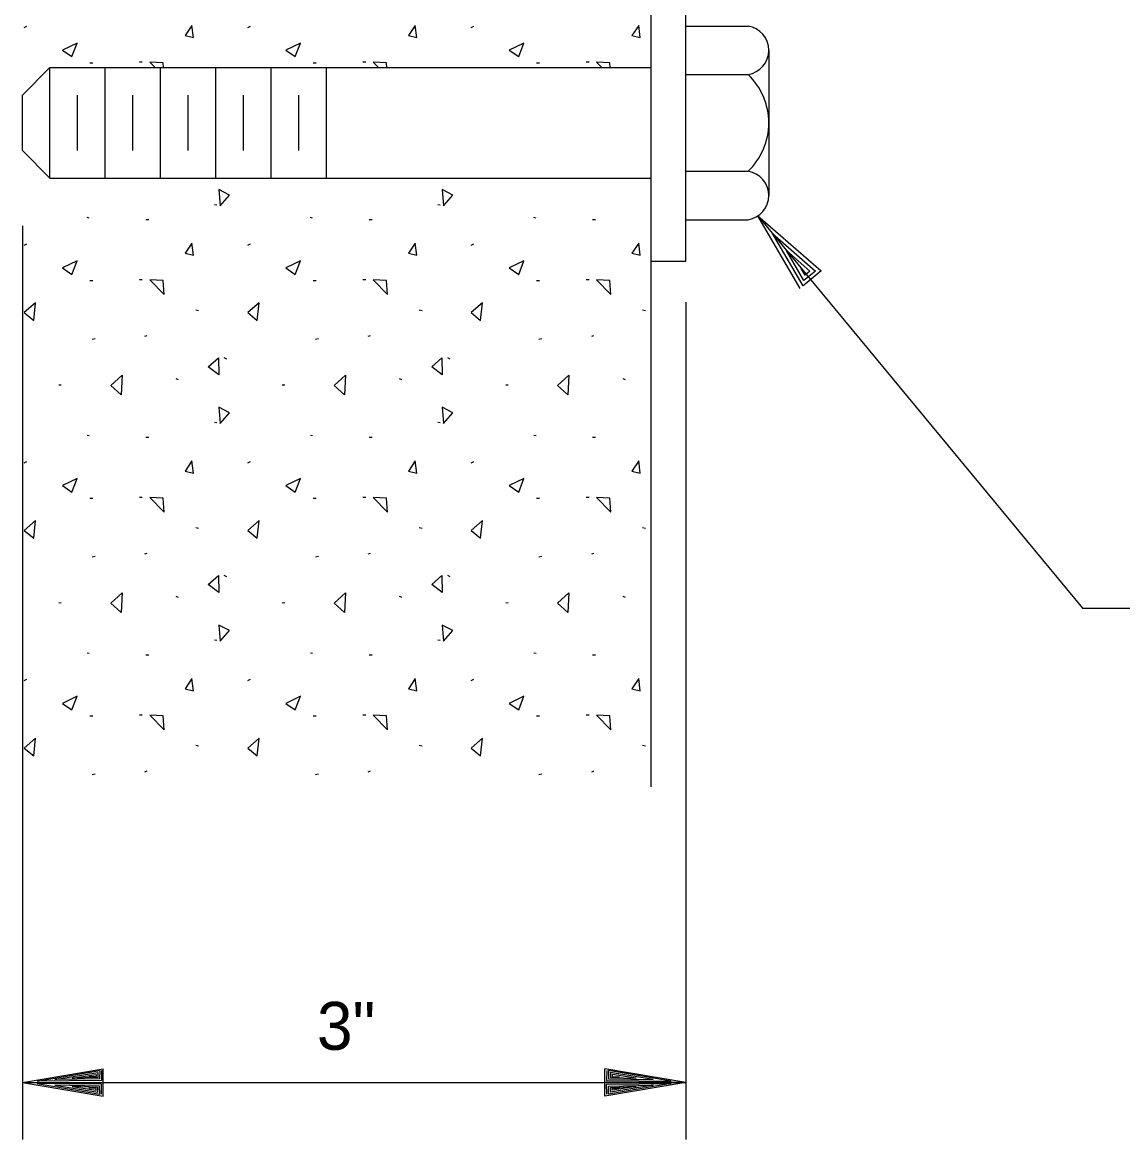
# Model space of a CAD drawing. Extents: x 44742.55 to 44745.38, y 44738.95 to 44741.13.
# Drawn here: x 44743.7411 to 44743.9484, y 44739.2677 to 44739.478 of the extents above; entities that cross this region are included whole.
import ezdxf

# ---------------------------------------------------------------- set-up
doc = ezdxf.new("R2010")
doc.units = 0
for name, color, linetype in [('G-ANNO-PATT', 7, 'Continuous'), ('Level 1', 7, 'Continuous'), ('Level 10', 7, 'Continuous'), ('Level 2', 7, 'Continuous'), ('Level 4', 7, 'Continuous')]:
    doc.layers.add(name, color=color, linetype=linetype)

msp = doc.modelspace()

# ---------------------------------------------------------------- linework, layer by layer
at = {"layer": 'G-ANNO-PATT'}
for p, q in [((44743.741951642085, 44739.47728637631), (44743.74145164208, 44739.4770363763)), ((44743.78403497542, 44739.47728637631), (44743.78353497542, 44739.4770363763)), ((44743.826118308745, 44739.47728637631), (44743.82561830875, 44739.4770363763)), ((44743.754409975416, 44739.470369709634), (44743.75384747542, 44739.470369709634)), ((44743.76374330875, 44739.470567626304), (44743.76321205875, 44739.470567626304)), ((44743.79649330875, 44739.470369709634), (44743.79593080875, 44739.470369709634)), ((44743.805826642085, 44739.470567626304), (44743.805295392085, 44739.470567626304)), ((44743.83857664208, 44739.470369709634), (44743.83801414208, 44739.470369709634)), ((44743.84790997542, 44739.470567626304), (44743.84737872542, 44739.470567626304)), ((44743.77777455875, 44739.44364054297), (44743.77735789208, 44739.44367179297)), ((44743.819857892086, 44739.44364054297), (44743.819441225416, 44739.44367179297)), ((44743.75374330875, 44739.44120304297), (44743.75332664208, 44739.44127595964)), ((44743.79582664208, 44739.44120304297), (44743.79540997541, 44739.44127595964)), ((44743.83790997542, 44739.44120304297), (44743.83749330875, 44739.44127595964)), ((44743.76495164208, 44739.4408488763), (44743.76438914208, 44739.4408488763)), ((44743.80703497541, 44739.4408488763), (44743.806472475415, 44739.4408488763)), ((44743.849118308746, 44739.4408488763), (44743.84855580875, 44739.4408488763)), ((44743.741951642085, 44739.43629679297), (44743.74145164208, 44739.43604679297)), ((44743.78403497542, 44739.43629679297), (44743.78353497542, 44739.43604679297)), ((44743.826118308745, 44739.43629679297), (44743.82561830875, 44739.43604679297)), ((44743.754409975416, 44739.429380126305), (44743.75384747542, 44739.429380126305)), ((44743.76374330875, 44739.42957804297), (44743.76321205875, 44739.42957804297)), ((44743.79649330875, 44739.429380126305), (44743.79593080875, 44739.429380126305)), ((44743.805826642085, 44739.42957804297), (44743.805295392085, 44739.42957804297)), ((44743.83857664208, 44739.429380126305), (44743.83801414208, 44739.429380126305)), ((44743.84790997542, 44739.42957804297), (44743.84737872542, 44739.42957804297)), ((44743.77434747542, 44739.42375512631), (44743.77380580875, 44739.4238488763)), ((44743.81643080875, 44739.42375512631), (44743.81588914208, 44739.4238488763)), ((44743.858514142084, 44739.42375512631), (44743.857972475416, 44739.4238488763)), ((44743.75485789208, 44739.4184738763), (44743.75429539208, 44739.4183176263)), ((44743.764566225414, 44739.419036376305), (44743.76415997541, 44739.4188801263)), ((44743.79694122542, 44739.4184738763), (44743.79637872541, 44739.4183176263)), ((44743.80664955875, 44739.419036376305), (44743.80624330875, 44739.4188801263)), ((44743.83902455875, 44739.4184738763), (44743.838462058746, 44739.4183176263)), ((44743.84873289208, 44739.419036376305), (44743.84832664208, 44739.4188801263)), ((44743.779649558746, 44739.414619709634), (44743.77918080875, 44739.41490095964)), ((44743.82173289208, 44739.414619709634), (44743.82126414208, 44739.41490095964)), ((44743.74848289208, 44739.409744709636), (44743.74802455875, 44739.40970304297)), ((44743.770576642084, 44739.41074470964), (44743.77012872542, 44739.41095304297)), ((44743.79056622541, 44739.409744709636), (44743.790107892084, 44739.40970304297)), ((44743.81265997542, 44739.41074470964), (44743.81221205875, 44739.41095304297)), ((44743.832649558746, 44739.409744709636), (44743.83219122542, 44739.40970304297)), ((44743.85474330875, 44739.41074470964), (44743.854295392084, 44739.41095304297)), ((44743.77777455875, 44739.40265095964), (44743.77735789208, 44739.402682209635)), ((44743.819857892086, 44739.40265095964), (44743.819441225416, 44739.402682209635)), ((44743.75374330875, 44739.40021345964), (44743.75332664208, 44739.4002863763)), ((44743.76495164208, 44739.39985929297), (44743.76438914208, 44739.39985929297)), ((44743.79582664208, 44739.40021345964), (44743.79540997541, 44739.4002863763)), ((44743.80703497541, 44739.39985929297), (44743.806472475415, 44739.39985929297)), ((44743.83790997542, 44739.40021345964), (44743.83749330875, 44739.4002863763)), ((44743.849118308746, 44739.39985929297), (44743.84855580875, 44739.39985929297)), ((44743.741951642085, 44739.395307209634), (44743.74145164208, 44739.39505720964)), ((44743.78403497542, 44739.395307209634), (44743.78353497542, 44739.39505720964)), ((44743.826118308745, 44739.395307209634), (44743.82561830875, 44739.39505720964)), ((44743.754409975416, 44739.38839054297), (44743.75384747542, 44739.38839054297)), ((44743.76374330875, 44739.38858845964), (44743.76321205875, 44739.38858845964)), ((44743.79649330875, 44739.38839054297), (44743.79593080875, 44739.38839054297)), ((44743.805826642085, 44739.38858845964), (44743.805295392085, 44739.38858845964)), ((44743.83857664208, 44739.38839054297), (44743.83801414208, 44739.38839054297)), ((44743.84790997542, 44739.38858845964), (44743.84737872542, 44739.38858845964)), ((44743.77434747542, 44739.38276554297), (44743.77380580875, 44739.38285929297)), ((44743.81643080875, 44739.38276554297), (44743.81588914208, 44739.38285929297)), ((44743.858514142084, 44739.38276554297), (44743.857972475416, 44739.38285929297)), ((44743.75485789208, 44739.37748429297), (44743.75429539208, 44739.37732804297)), ((44743.764566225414, 44739.37804679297), (44743.76415997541, 44739.37789054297)), ((44743.79694122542, 44739.37748429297), (44743.79637872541, 44739.37732804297)), ((44743.80664955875, 44739.37804679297), (44743.80624330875, 44739.37789054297)), ((44743.83902455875, 44739.37748429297), (44743.838462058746, 44739.37732804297)), ((44743.84873289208, 44739.37804679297), (44743.84832664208, 44739.37789054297)), ((44743.779649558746, 44739.373630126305), (44743.77918080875, 44739.3739113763)), ((44743.82173289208, 44739.373630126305), (44743.82126414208, 44739.3739113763)), ((44743.770576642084, 44739.3697551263), (44743.77012872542, 44739.369963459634)), ((44743.81265997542, 44739.3697551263), (44743.81221205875, 44739.369963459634)), ((44743.74848289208, 44739.36875512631), (44743.74802455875, 44739.36871345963)), ((44743.79056622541, 44739.36875512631), (44743.790107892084, 44739.36871345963)), ((44743.832649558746, 44739.36875512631), (44743.83219122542, 44739.36871345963)), ((44743.77777455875, 44739.3616613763), (44743.77735789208, 44739.361692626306)), ((44743.819857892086, 44739.3616613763), (44743.819441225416, 44739.361692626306)), ((44743.75374330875, 44739.3592238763), (44743.75332664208, 44739.35929679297)), ((44743.79582664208, 44739.3592238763), (44743.79540997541, 44739.35929679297)), ((44743.83790997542, 44739.3592238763), (44743.83749330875, 44739.35929679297)), ((44743.76495164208, 44739.358869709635), (44743.76438914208, 44739.358869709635)), ((44743.80703497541, 44739.358869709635), (44743.806472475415, 44739.358869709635)), ((44743.849118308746, 44739.358869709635), (44743.84855580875, 44739.358869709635)), ((44743.741951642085, 44739.354317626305), (44743.74145164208, 44739.3540676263)), ((44743.78403497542, 44739.354317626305), (44743.78353497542, 44739.3540676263)), ((44743.826118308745, 44739.354317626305), (44743.82561830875, 44739.3540676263)), ((44743.754409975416, 44739.34740095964), (44743.75384747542, 44739.34740095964)), ((44743.76374330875, 44739.3475988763), (44743.76321205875, 44739.3475988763)), ((44743.79649330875, 44739.34740095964), (44743.79593080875, 44739.34740095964)), ((44743.805826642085, 44739.3475988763), (44743.805295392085, 44739.3475988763)), ((44743.83857664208, 44739.34740095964), (44743.83801414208, 44739.34740095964)), ((44743.84790997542, 44739.3475988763), (44743.84737872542, 44739.3475988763)), ((44743.77434747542, 44739.341775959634), (44743.77380580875, 44739.341869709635)), ((44743.81643080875, 44739.341775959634), (44743.81588914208, 44739.341869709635)), ((44743.858514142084, 44739.341775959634), (44743.857972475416, 44739.341869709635)), ((44743.75485789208, 44739.336494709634), (44743.75429539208, 44739.33633845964)), ((44743.764566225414, 44739.33705720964), (44743.76415997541, 44739.336900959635)), ((44743.79694122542, 44739.336494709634), (44743.79637872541, 44739.33633845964)), ((44743.80664955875, 44739.33705720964), (44743.80624330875, 44739.336900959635)), ((44743.83902455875, 44739.336494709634), (44743.838462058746, 44739.33633845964)), ((44743.84873289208, 44739.33705720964), (44743.84832664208, 44739.336900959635))]:
    msp.add_line(p, q, dxfattribs=at)
for points in [[(44743.77336830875, 44739.47517179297), (44743.77307664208, 44739.47745304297), (44743.77179539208, 44739.47554679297)], [(44743.815451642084, 44739.47517179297), (44743.81515997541, 44739.47745304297), (44743.813878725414, 44739.47554679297)], [(44743.85753497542, 44739.47517179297), (44743.85724330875, 44739.47745304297), (44743.85596205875, 44739.47554679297)], [(44743.75047247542, 44739.47158845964), (44743.751462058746, 44739.47414054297), (44743.748701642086, 44739.47279679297)], [(44743.79255580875, 44739.47158845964), (44743.79354539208, 44739.47414054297), (44743.79078497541, 44739.47279679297)], [(44743.834639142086, 44739.47158845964), (44743.835628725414, 44739.47414054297), (44743.832868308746, 44739.47279679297)], [(44743.778378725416, 44739.44349470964), (44743.78015997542, 44739.44549470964), (44743.778170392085, 44739.44655720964)], [(44743.82046205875, 44739.44349470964), (44743.82224330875, 44739.44549470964), (44743.82025372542, 44739.44655720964)], [(44743.77336830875, 44739.43418220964), (44743.77307664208, 44739.436463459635), (44743.77179539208, 44739.434557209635)], [(44743.815451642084, 44739.43418220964), (44743.81515997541, 44739.436463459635), (44743.813878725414, 44739.434557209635)], [(44743.85753497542, 44739.43418220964), (44743.85724330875, 44739.436463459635), (44743.85596205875, 44739.434557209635)], [(44743.75047247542, 44739.4305988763), (44743.751462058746, 44739.43315095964), (44743.748701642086, 44739.431807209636)], [(44743.79255580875, 44739.4305988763), (44743.79354539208, 44739.43315095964), (44743.79078497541, 44739.431807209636)], [(44743.834639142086, 44739.4305988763), (44743.835628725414, 44739.43315095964), (44743.832868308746, 44739.431807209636)], [(44743.76764955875, 44739.4294426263), (44743.76514955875, 44739.42957804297), (44743.76785789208, 44739.42680720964)], [(44743.809732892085, 44739.4294426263), (44743.80723289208, 44739.42957804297), (44743.809941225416, 44739.42680720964)], [(44743.85181622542, 44739.4294426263), (44743.849316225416, 44739.42957804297), (44743.85202455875, 44739.42680720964)], [(44743.743639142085, 44739.425255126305), (44743.74150372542, 44739.42339054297), (44743.74327455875, 44739.421900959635)], [(44743.78572247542, 44739.425255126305), (44743.78358705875, 44739.42339054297), (44743.785357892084, 44739.421900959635)], [(44743.827805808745, 44739.425255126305), (44743.825670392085, 44739.42339054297), (44743.82744122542, 44739.421900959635)], [(44743.778170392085, 44739.41167179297), (44743.776170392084, 44739.41318220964), (44743.77808705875, 44739.4148801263)], [(44743.82025372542, 44739.41167179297), (44743.81825372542, 44739.41318220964), (44743.82017039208, 44739.4148801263)], [(44743.75974330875, 44739.4079113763), (44743.757816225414, 44739.4096926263), (44743.75995164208, 44739.4115988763)], [(44743.801826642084, 44739.4079113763), (44743.79989955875, 44739.4096926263), (44743.802034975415, 44739.4115988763)], [(44743.84390997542, 44739.4079113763), (44743.84198289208, 44739.4096926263), (44743.84411830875, 44739.4115988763)], [(44743.778378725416, 44739.4025051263), (44743.78015997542, 44739.4045051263), (44743.778170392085, 44739.4055676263)], [(44743.82046205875, 44739.4025051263), (44743.82224330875, 44739.4045051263), (44743.82025372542, 44739.4055676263)], [(44743.77336830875, 44739.3931926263), (44743.77307664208, 44739.395473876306), (44743.77179539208, 44739.393567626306)], [(44743.815451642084, 44739.3931926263), (44743.81515997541, 44739.395473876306), (44743.813878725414, 44739.393567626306)], [(44743.85753497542, 44739.3931926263), (44743.85724330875, 44739.395473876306), (44743.85596205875, 44739.393567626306)], [(44743.75047247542, 44739.38960929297), (44743.751462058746, 44739.3921613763), (44743.748701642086, 44739.39081762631)], [(44743.79255580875, 44739.38960929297), (44743.79354539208, 44739.3921613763), (44743.79078497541, 44739.39081762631)], [(44743.834639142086, 44739.38960929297), (44743.835628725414, 44739.3921613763), (44743.832868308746, 44739.39081762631)], [(44743.76764955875, 44739.38845304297), (44743.76514955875, 44739.38858845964), (44743.76785789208, 44739.3858176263)], [(44743.809732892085, 44739.38845304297), (44743.80723289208, 44739.38858845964), (44743.809941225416, 44739.3858176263)], [(44743.85181622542, 44739.38845304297), (44743.849316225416, 44739.38858845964), (44743.85202455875, 44739.3858176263)], [(44743.743639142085, 44739.38426554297), (44743.74150372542, 44739.382400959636), (44743.74327455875, 44739.380911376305)], [(44743.78572247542, 44739.38426554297), (44743.78358705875, 44739.382400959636), (44743.785357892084, 44739.380911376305)], [(44743.827805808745, 44739.38426554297), (44743.825670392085, 44739.382400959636), (44743.82744122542, 44739.380911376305)], [(44743.778170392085, 44739.370682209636), (44743.776170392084, 44739.3721926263), (44743.77808705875, 44739.37389054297)], [(44743.82025372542, 44739.370682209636), (44743.81825372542, 44739.3721926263), (44743.82017039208, 44739.37389054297)], [(44743.75974330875, 44739.36692179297), (44743.757816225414, 44739.36870304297), (44743.75995164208, 44739.37060929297)], [(44743.801826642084, 44739.36692179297), (44743.79989955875, 44739.36870304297), (44743.802034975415, 44739.37060929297)], [(44743.84390997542, 44739.36692179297), (44743.84198289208, 44739.36870304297), (44743.84411830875, 44739.37060929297)], [(44743.778378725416, 44739.36151554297), (44743.78015997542, 44739.36351554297), (44743.778170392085, 44739.36457804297)], [(44743.82046205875, 44739.36151554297), (44743.82224330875, 44739.36351554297), (44743.82025372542, 44739.36457804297)], [(44743.77336830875, 44739.35220304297), (44743.77307664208, 44739.35448429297), (44743.77179539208, 44739.35257804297)], [(44743.815451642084, 44739.35220304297), (44743.81515997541, 44739.35448429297), (44743.813878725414, 44739.35257804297)], [(44743.85753497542, 44739.35220304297), (44743.85724330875, 44739.35448429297), (44743.85596205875, 44739.35257804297)], [(44743.75047247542, 44739.348619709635), (44743.751462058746, 44739.35117179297), (44743.748701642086, 44739.34982804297)], [(44743.79255580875, 44739.348619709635), (44743.79354539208, 44739.35117179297), (44743.79078497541, 44739.34982804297)], [(44743.834639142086, 44739.348619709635), (44743.835628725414, 44739.35117179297), (44743.832868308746, 44739.34982804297)], [(44743.76764955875, 44739.347463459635), (44743.76514955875, 44739.3475988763), (44743.76785789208, 44739.34482804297)], [(44743.809732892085, 44739.347463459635), (44743.80723289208, 44739.3475988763), (44743.809941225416, 44739.34482804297)], [(44743.85181622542, 44739.347463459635), (44743.849316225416, 44739.3475988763), (44743.85202455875, 44739.34482804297)], [(44743.743639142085, 44739.34327595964), (44743.74150372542, 44739.34141137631), (44743.74327455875, 44739.33992179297)], [(44743.78572247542, 44739.34327595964), (44743.78358705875, 44739.34141137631), (44743.785357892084, 44739.33992179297)], [(44743.827805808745, 44739.34327595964), (44743.825670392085, 44739.34141137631), (44743.82744122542, 44739.33992179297)]]:
    msp.add_lwpolyline(points, close=True, dxfattribs=at)
for points in [[(44743.76764955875, 44739.47043220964), (44743.76514955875, 44739.470567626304), (44743.766159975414, 44739.4695363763)], [(44743.809732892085, 44739.47043220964), (44743.80723289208, 44739.470567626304), (44743.80824330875, 44739.4695363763)], [(44743.80980580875, 44739.4695363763), (44743.809732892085, 44739.47043220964)], [(44743.85181622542, 44739.47043220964), (44743.849316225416, 44739.470567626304), (44743.85032664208, 44739.4695363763)], [(44743.85188914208, 44739.4695363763), (44743.85181622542, 44739.47043220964)]]:
    msp.add_lwpolyline(points, dxfattribs=at)
at = {"layer": 'Level 1'}
for p, q in [((44743.87969122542, 44739.44159887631), (44743.87969122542, 44739.44159887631)), ((44743.74113914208, 44739.439723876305), (44743.74113914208, 44739.26768220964)), ((44743.88245164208, 44739.43826554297), (44743.88245164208, 44739.43826554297)), ((44743.866128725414, 44739.425369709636), (44743.866128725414, 44739.26768220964)), ((44743.85474330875, 44739.3697551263), (44743.854295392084, 44739.369963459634)), ((44743.74113914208, 44739.27846345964), (44743.75637872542, 44739.28104679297)), ((44743.74393080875, 44739.27867179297), (44743.75571205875, 44739.28067179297)), ((44743.74728497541, 44739.27898429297), (44743.755357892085, 44739.280317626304)), ((44743.750524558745, 44739.279255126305), (44743.75503497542, 44739.2799426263)), ((44743.755045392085, 44739.2795988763), (44743.75364955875, 44739.27952595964)), ((44743.75503497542, 44739.2799426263), (44743.755045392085, 44739.2795988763)), ((44743.75571205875, 44739.28067179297), (44743.755691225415, 44739.27914054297)), ((44743.75604539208, 44739.28067179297), (44743.75606622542, 44739.27882804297)), ((44743.75637872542, 44739.275869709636), (44743.75637872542, 44739.28104679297)), ((44743.85088914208, 44739.275869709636), (44743.85088914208, 44739.28104679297)), ((44743.866128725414, 44739.27846345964), (44743.85088914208, 44739.28104679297)), ((44743.851222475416, 44739.28067179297), (44743.85121205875, 44739.27882804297)), ((44743.86333705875, 44739.27867179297), (44743.851555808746, 44739.28067179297)), ((44743.859982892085, 44739.27898429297), (44743.85192039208, 44739.280317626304)), ((44743.85192039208, 44739.280317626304), (44743.85192039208, 44739.2794113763)), ((44743.85192039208, 44739.2794113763), (44743.85674330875, 44739.279255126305)), ((44743.85223289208, 44739.2799426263), (44743.85222247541, 44739.2795988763)), ((44743.85222247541, 44739.2795988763), (44743.85362872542, 44739.27952595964)), ((44743.85674330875, 44739.279255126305), (44743.85223289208, 44739.2799426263)), ((44743.74113914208, 44739.27846345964), (44743.866128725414, 44739.27846345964)), ((44743.74113914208, 44739.27846345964), (44743.75637872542, 44739.27846345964)), ((44743.74113914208, 44739.27846345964), (44743.75637872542, 44739.275869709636)), ((44743.75606622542, 44739.27882804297), (44743.74393080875, 44739.27867179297)), ((44743.75606622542, 44739.278098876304), (44743.74393080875, 44739.27824470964)), ((44743.74393080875, 44739.27824470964), (44743.75571205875, 44739.27624470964)), ((44743.755691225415, 44739.27914054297), (44743.74728497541, 44739.27898429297)), ((44743.74728497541, 44739.27793220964), (44743.755357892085, 44739.276598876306)), ((44743.755691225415, 44739.277775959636), (44743.74728497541, 44739.27793220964)), ((44743.750524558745, 44739.277661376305), (44743.75503497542, 44739.2769738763)), ((44743.75534747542, 44739.2775051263), (44743.750524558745, 44739.277661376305)), ((44743.755045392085, 44739.2773176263), (44743.75364955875, 44739.27739054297)), ((44743.75503497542, 44739.2769738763), (44743.755045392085, 44739.2773176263)), ((44743.755357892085, 44739.276598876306), (44743.75534747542, 44739.2775051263)), ((44743.75571205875, 44739.27624470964), (44743.755691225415, 44739.277775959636)), ((44743.75604539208, 44739.27624470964), (44743.75606622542, 44739.278098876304)), ((44743.866128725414, 44739.27846345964), (44743.85088914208, 44739.27846345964)), ((44743.866128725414, 44739.27846345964), (44743.85088914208, 44739.275869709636)), ((44743.85121205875, 44739.27882804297), (44743.86333705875, 44739.27867179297)), ((44743.85121205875, 44739.278098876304), (44743.86333705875, 44739.27824470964)), ((44743.851222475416, 44739.27624470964), (44743.85121205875, 44739.278098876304)), ((44743.86333705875, 44739.27824470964), (44743.851555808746, 44739.27624470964)), ((44743.851555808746, 44739.27624470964), (44743.85157664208, 44739.277775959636)), ((44743.85157664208, 44739.27914054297), (44743.859982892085, 44739.27898429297)), ((44743.85157664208, 44739.277775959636), (44743.859982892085, 44739.27793220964)), ((44743.859982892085, 44739.27793220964), (44743.85192039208, 44739.276598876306)), ((44743.85192039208, 44739.2775051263), (44743.85674330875, 44739.277661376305)), ((44743.85192039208, 44739.276598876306), (44743.85192039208, 44739.2775051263)), ((44743.85222247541, 44739.2773176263), (44743.85362872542, 44739.27739054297)), ((44743.85223289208, 44739.2769738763), (44743.85222247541, 44739.2773176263)), ((44743.85674330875, 44739.277661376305), (44743.85223289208, 44739.2769738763))]:
    msp.add_line(p, q, dxfattribs=at)
for points in [[(44743.767722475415, 44739.4695363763), (44743.76764955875, 44739.47043220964)], [(44743.87969122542, 44739.44159887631), (44743.94084747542, 44739.36776554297), (44743.96553497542, 44739.36776554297)], [(44743.887639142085, 44739.42795304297), (44743.87969122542, 44739.44159887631), (44743.89161830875, 44739.43124470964), (44743.88822247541, 44739.428432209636), (44743.88245164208, 44739.43826554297), (44743.89055580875, 44739.4312238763), (44743.88836830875, 44739.42942179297), (44743.885118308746, 44739.43505720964), (44743.88948289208, 44739.43121345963), (44743.88858705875, 44739.430463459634), (44743.887878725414, 44739.431713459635)]]:
    msp.add_lwpolyline(points, dxfattribs=at)
at = {"layer": 'Level 10'}
msp.add_line((44743.85962872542, 44739.33411970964), (44743.85962872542, 44739.58410929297), dxfattribs=at)
at = {"layer": 'Level 2'}
for p, q in [((44743.866128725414, 44739.43307804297), (44743.866128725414, 44739.50598429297)), ((44743.866128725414, 44739.4773488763), (44743.877847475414, 44739.4773488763)), ((44743.881753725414, 44739.472786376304), (44743.881753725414, 44739.445442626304)), ((44743.74113914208, 44739.46432804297), (44743.74634747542, 44739.4695363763)), ((44743.74634747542, 44739.4695363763), (44743.85962872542, 44739.4695363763)), ((44743.74634747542, 44739.44870304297), (44743.74634747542, 44739.4695363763)), ((44743.75676414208, 44739.44870304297), (44743.75676414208, 44739.4695363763)), ((44743.76718080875, 44739.44870304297), (44743.76718080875, 44739.4695363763)), ((44743.77759747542, 44739.44870304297), (44743.77759747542, 44739.4695363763)), ((44743.78801414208, 44739.44870304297), (44743.78801414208, 44739.4695363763)), ((44743.79843080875, 44739.44870304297), (44743.79843080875, 44739.4695363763)), ((44743.866128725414, 44739.46823429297), (44743.877847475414, 44739.46823429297)), ((44743.74113914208, 44739.4539113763), (44743.74113914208, 44739.46432804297)), ((44743.75155580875, 44739.4539113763), (44743.75155580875, 44739.46432804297)), ((44743.76197247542, 44739.4539113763), (44743.76197247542, 44739.46432804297)), ((44743.77238914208, 44739.4539113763), (44743.77238914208, 44739.46432804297)), ((44743.78280580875, 44739.4539113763), (44743.78280580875, 44739.46432804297)), ((44743.79322247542, 44739.4539113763), (44743.79322247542, 44739.46432804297)), ((44743.74634747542, 44739.44870304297), (44743.74113914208, 44739.4539113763)), ((44743.866128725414, 44739.4500051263), (44743.877847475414, 44739.4500051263)), ((44743.74634747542, 44739.44870304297), (44743.85962872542, 44739.44870304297)), ((44743.866128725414, 44739.44089054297), (44743.877847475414, 44739.44089054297)), ((44743.85962872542, 44739.43307804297), (44743.866128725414, 44739.43307804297)), ((44743.75534747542, 44739.2794113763), (44743.750524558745, 44739.279255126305)), ((44743.755357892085, 44739.280317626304), (44743.75534747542, 44739.2794113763)), ((44743.851555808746, 44739.28067179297), (44743.85157664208, 44739.27914054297))]:
    msp.add_line(p, q, dxfattribs=at)
for centre, radius, start, end in [((44743.87714893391, 44739.47278697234), 0.004610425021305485, 278.7219527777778, 81.2780416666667), ((44743.869173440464, 44739.45911564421), 0.012582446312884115, 313.584375, 46.41561111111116), ((44743.87714893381, 44739.445444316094), 0.004610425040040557, 278.7219527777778, 81.2780416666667)]:
    msp.add_arc(centre, radius, start, end, dxfattribs=at)

# ---------------------------------------------------------------- texts
at = {"layer": 'Level 4'}
msp.add_text('3"', height=0.00902027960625, dxfattribs=at).set_placement((44743.796639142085, 44739.2845988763))

doc.saveas('drawing.dxf')
